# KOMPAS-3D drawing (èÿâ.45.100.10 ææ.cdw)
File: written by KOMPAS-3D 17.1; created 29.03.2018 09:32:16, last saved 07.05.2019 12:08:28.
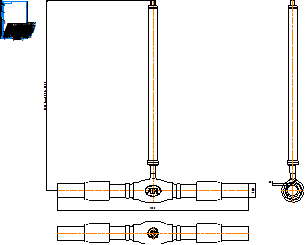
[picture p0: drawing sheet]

Sheet 1: A4, portrait

Title block, sheet 1: name: КШГ.45.100.10 СС; material: Внимание! Данный продукт является объектом авторского права ООО «Торговый Дом АДЛ». / Запрещается изменение, копирование, распространение / (в том числе путем копирования на другие сайты и ресурсы в Интернете) / или любое иное использование информации и объектов без предварительного / согласия правообладателя (ООО «Торговый Дом АДЛ»).; sheets: 1; organisation: ООО "Торговый дом АДЛ"; sheet format: A4; stored path: C:\Users\tra\Desktop\2д чертежи\Шаровые краны БИВАЛ\КШ_Бивал_серия_44_45_55\KOMPAS 2D\КШГ.45.100.10 СС.cdw

Views: Вид 1, Проекционный вид 2
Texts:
  kka
  adl
  (от 425 до 5000)
Dimensions and other numbers on the sheet: 1500; 110; 10; 1:1; 1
